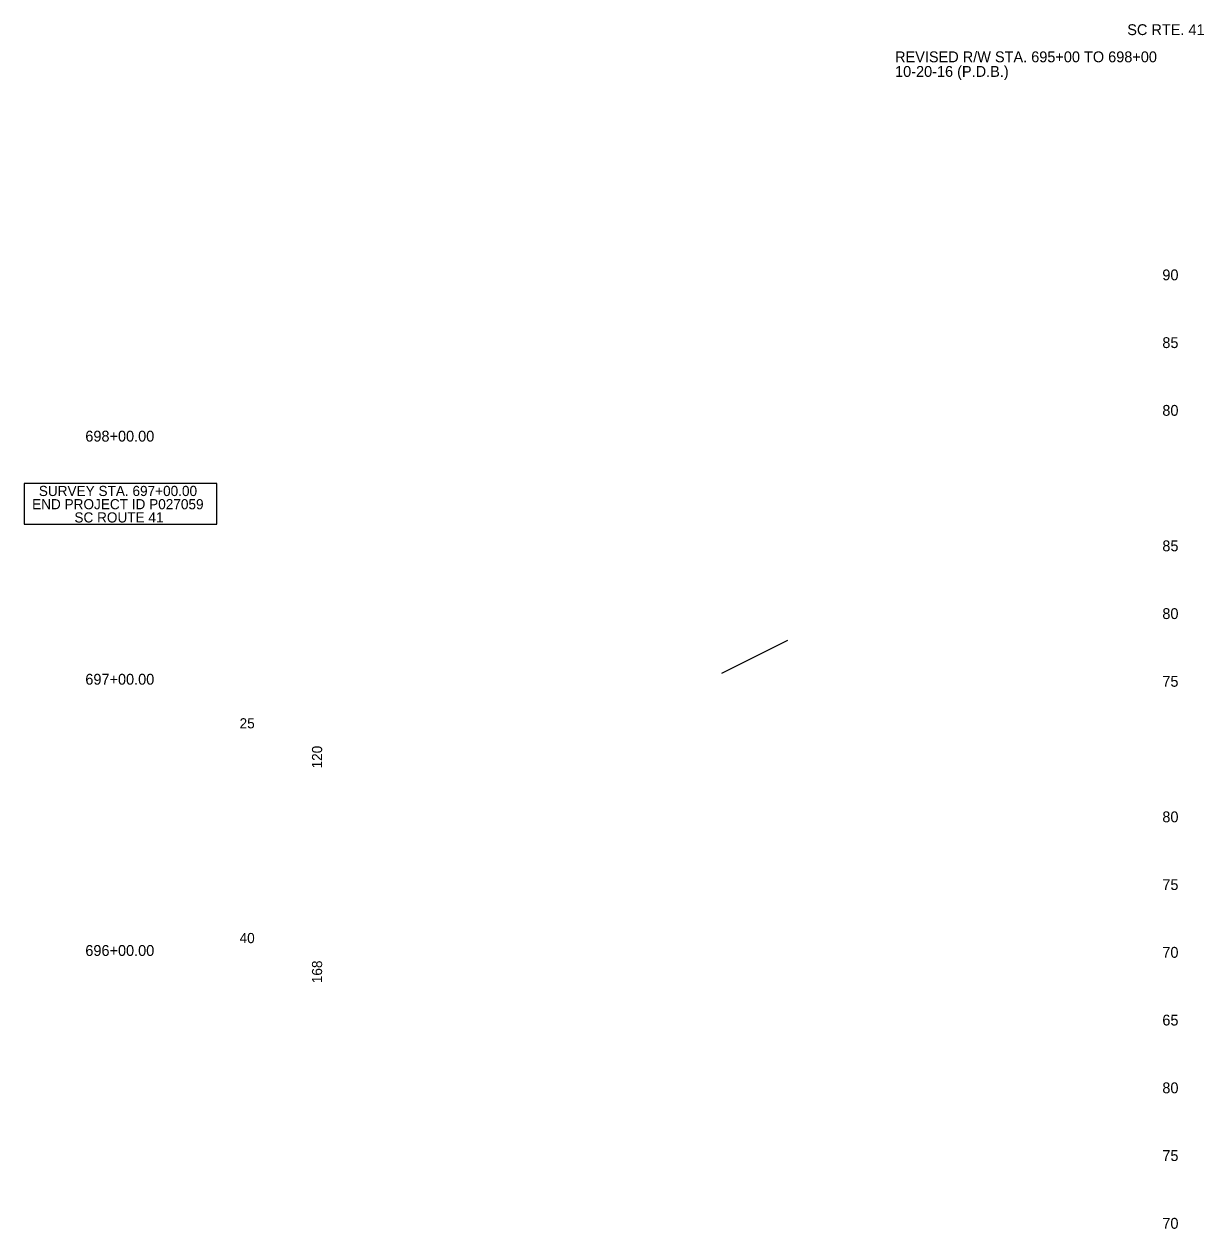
# Model space of a CAD drawing. Extents: x 952 to 1206, y 942 to 2399.
# Drawn here: x 1072.9 to 1160, y 2045 to 2133.9 of the extents above; entities that cross this region are included whole.
import ezdxf

# ---------------------------------------------------------------- set-up
doc = ezdxf.new("R2010")
doc.units = 0
for name, color, linetype in [('Default', 7, 'Continuous'), ('RD_SHT_TX', 7, 'Continuous'), ('RD_XS_TieSlope', 7, 'Continuous'), ('RD_XS_TX_Elev_EX', 7, 'Continuous'), ('RD_XS_TX_Station', 7, 'Continuous')]:
    doc.layers.add(name, color=color, linetype=linetype)

msp = doc.modelspace()

# ---------------------------------------------------------------- linework, layer by layer
at = {"layer": 'RD_SHT_TX'}
msp.add_lwpolyline([(1072.92, 2097), (1087.146, 2097), (1087.146, 2100), (1072.92, 2100)], close=True, dxfattribs=at)
at = {"layer": 'RD_XS_TieSlope'}
msp.add_line((1124.417, 2086.006), (1129.269, 2088.432), dxfattribs=at)

# ---------------------------------------------------------------- texts
at = {"layer": 'Default'}
for s, p in [('25', (1088.823, 2081.93)), ('40', (1088.823, 2066.08))]:
    msp.add_text(s, height=0.75, dxfattribs=at).set_placement(p)
for s, p in [('120', (1094.913, 2078.973)), ('168', (1094.913, 2063.123))]:
    msp.add_text(s, height=0.75, rotation=90, dxfattribs=at).set_placement(p)
at = {"layer": 'RD_SHT_TX'}
for s, height, p in [('SC RTE. 41', 0.8, (1154.33, 2133.098)), ('REVISED R/W STA. 695+00 TO 698+00', 0.8, (1137.195, 2131.093)), ('10-20-16 (P.D.B.)', 0.8, (1137.195, 2130.015)), ('SURVEY STA. 697+00.00', 0.75, (1074.006, 2099.078)), ('END PROJECT ID P027059', 0.75, (1073.511, 2098.102)), ('SC ROUTE 41', 0.75, (1076.633, 2097.125))]:
    msp.add_text(s, height=height, dxfattribs=at).set_placement(p)
at = {"layer": 'RD_XS_TX_Elev_EX'}
for s, p in [('90', (1156.919, 2115)), ('85', (1156.919, 2110)), ('80', (1156.919, 2105)), ('85', (1156.919, 2095)), ('80', (1156.919, 2090)), ('75', (1156.919, 2085)), ('80', (1156.919, 2075)), ('75', (1156.919, 2070)), ('70', (1156.919, 2065)), ('65', (1156.919, 2060)), ('80', (1156.919, 2055)), ('75', (1156.919, 2050)), ('70', (1156.919, 2045))]:
    msp.add_text(s, height=0.8, dxfattribs=at).set_placement(p)
at = {"layer": 'RD_XS_TX_Station'}
for s, p in [('698+00.00', (1077.439, 2103.097)), ('697+00.00', (1077.439, 2085.156)), ('696+00.00', (1077.439, 2065.136))]:
    msp.add_text(s, height=0.8, dxfattribs=at).set_placement(p)

doc.saveas('drawing.dxf')
